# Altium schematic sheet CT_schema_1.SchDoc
size 538 x 519 mm
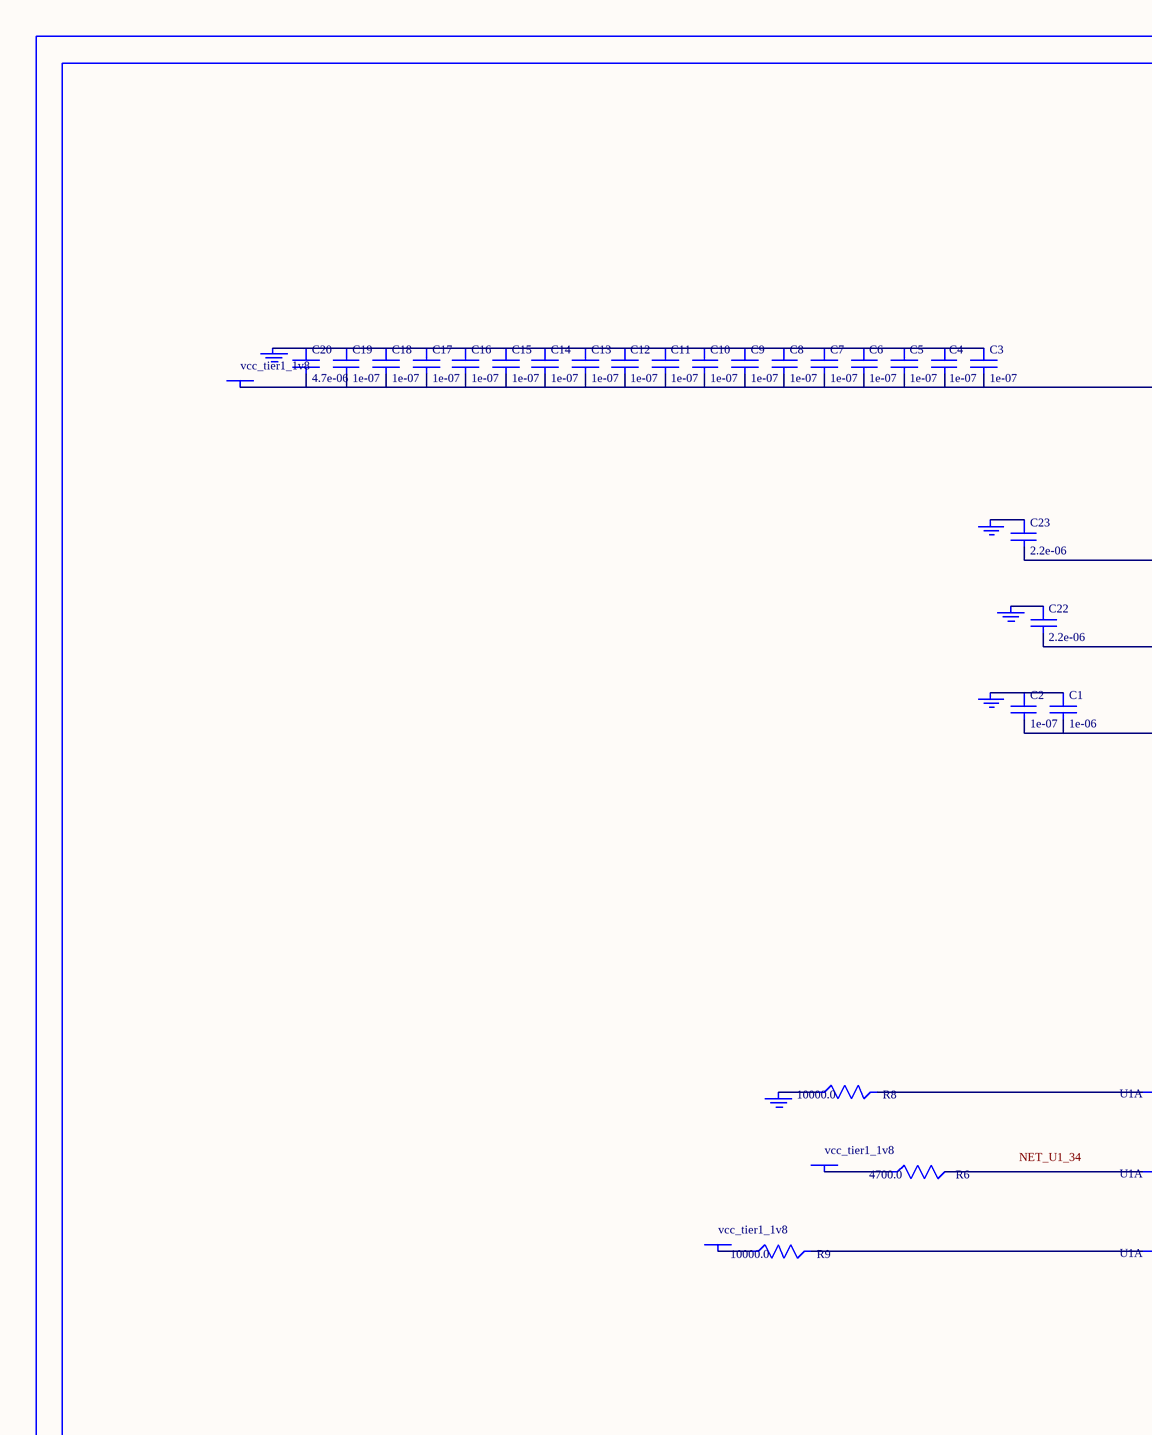
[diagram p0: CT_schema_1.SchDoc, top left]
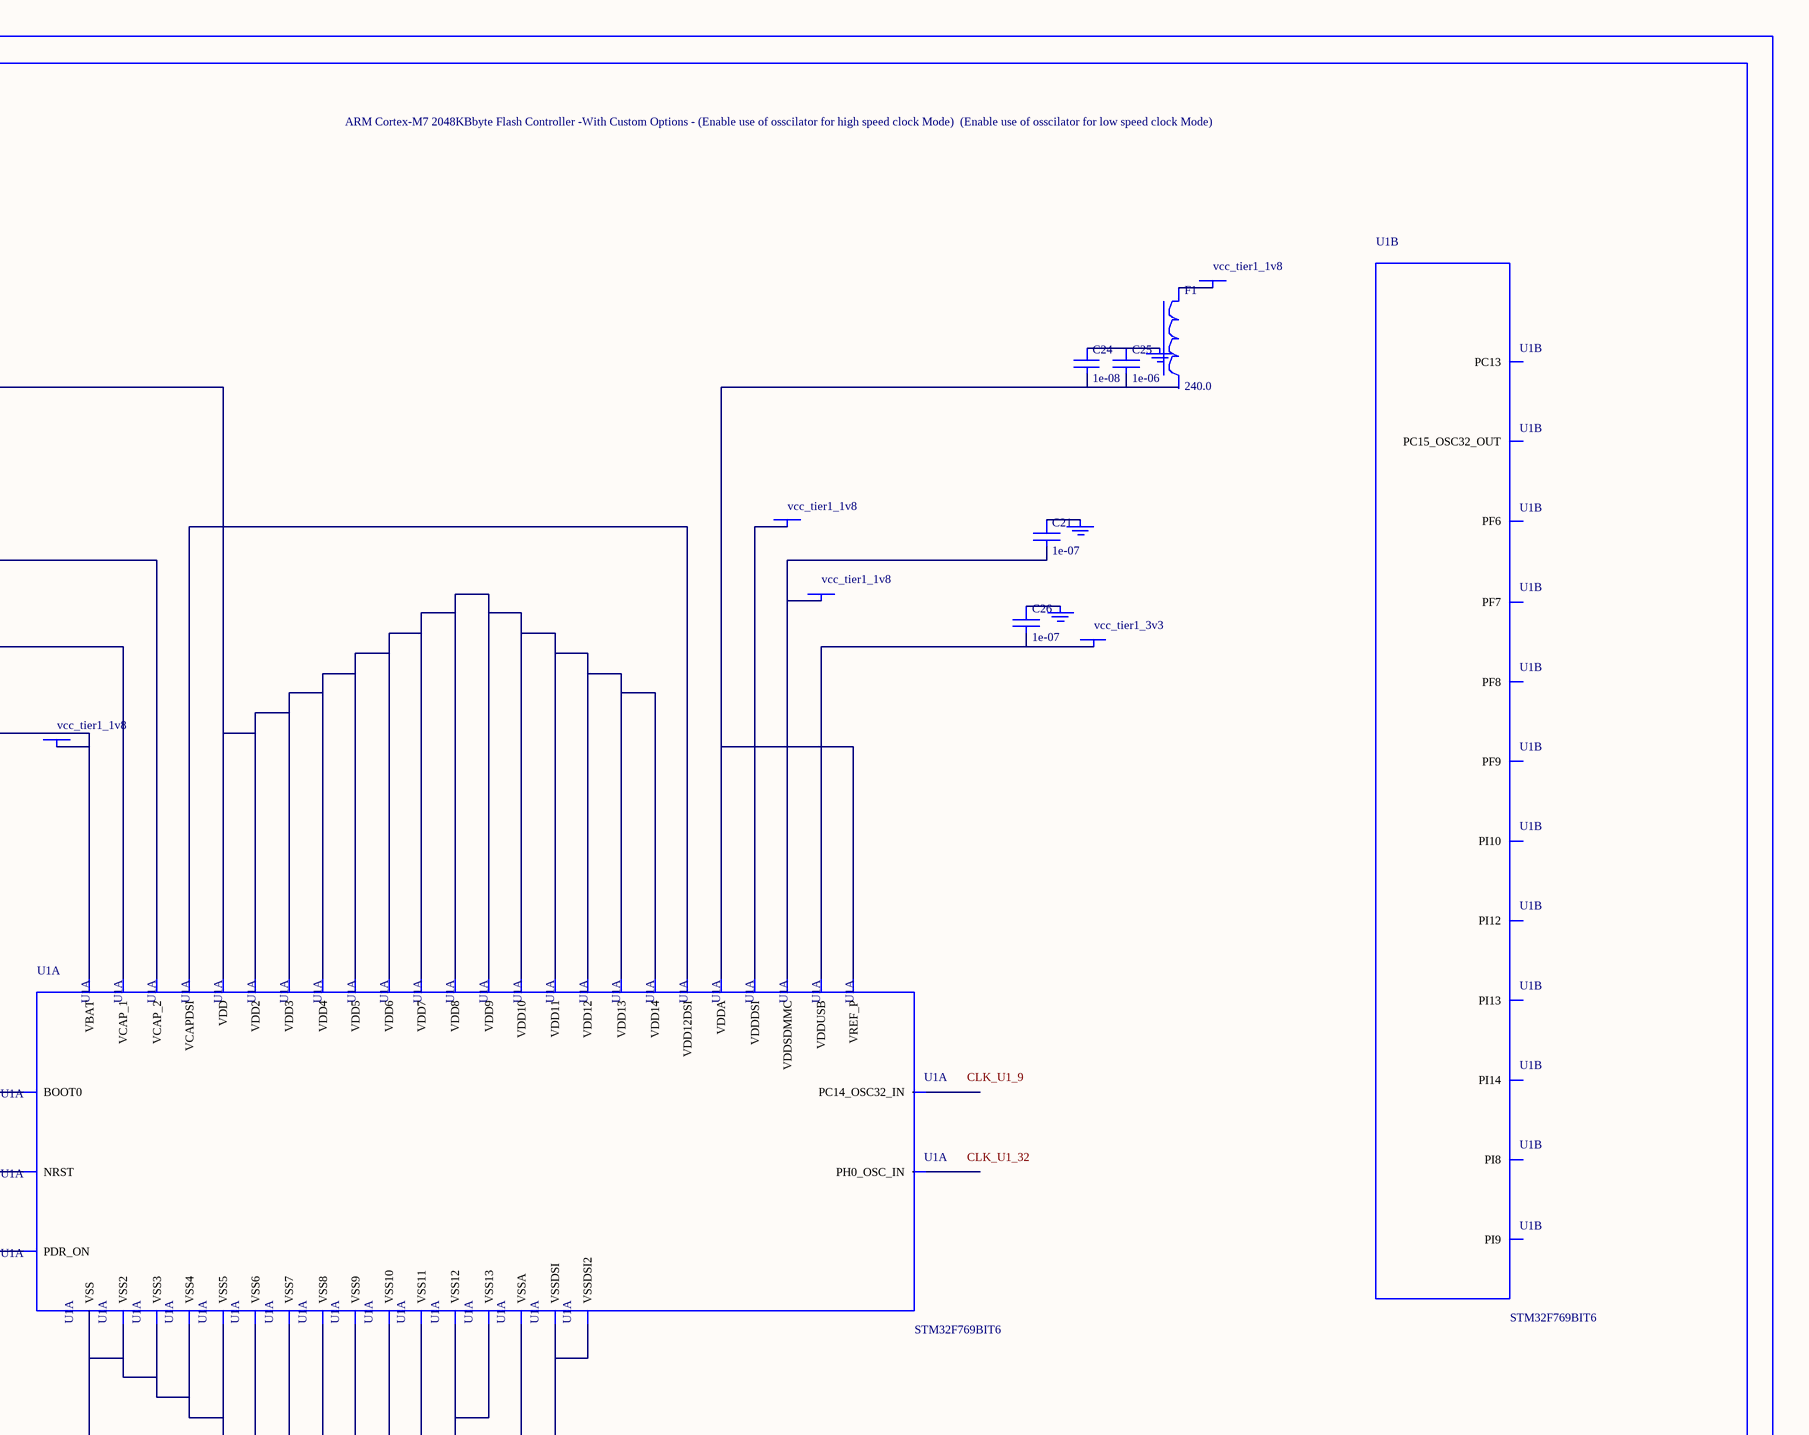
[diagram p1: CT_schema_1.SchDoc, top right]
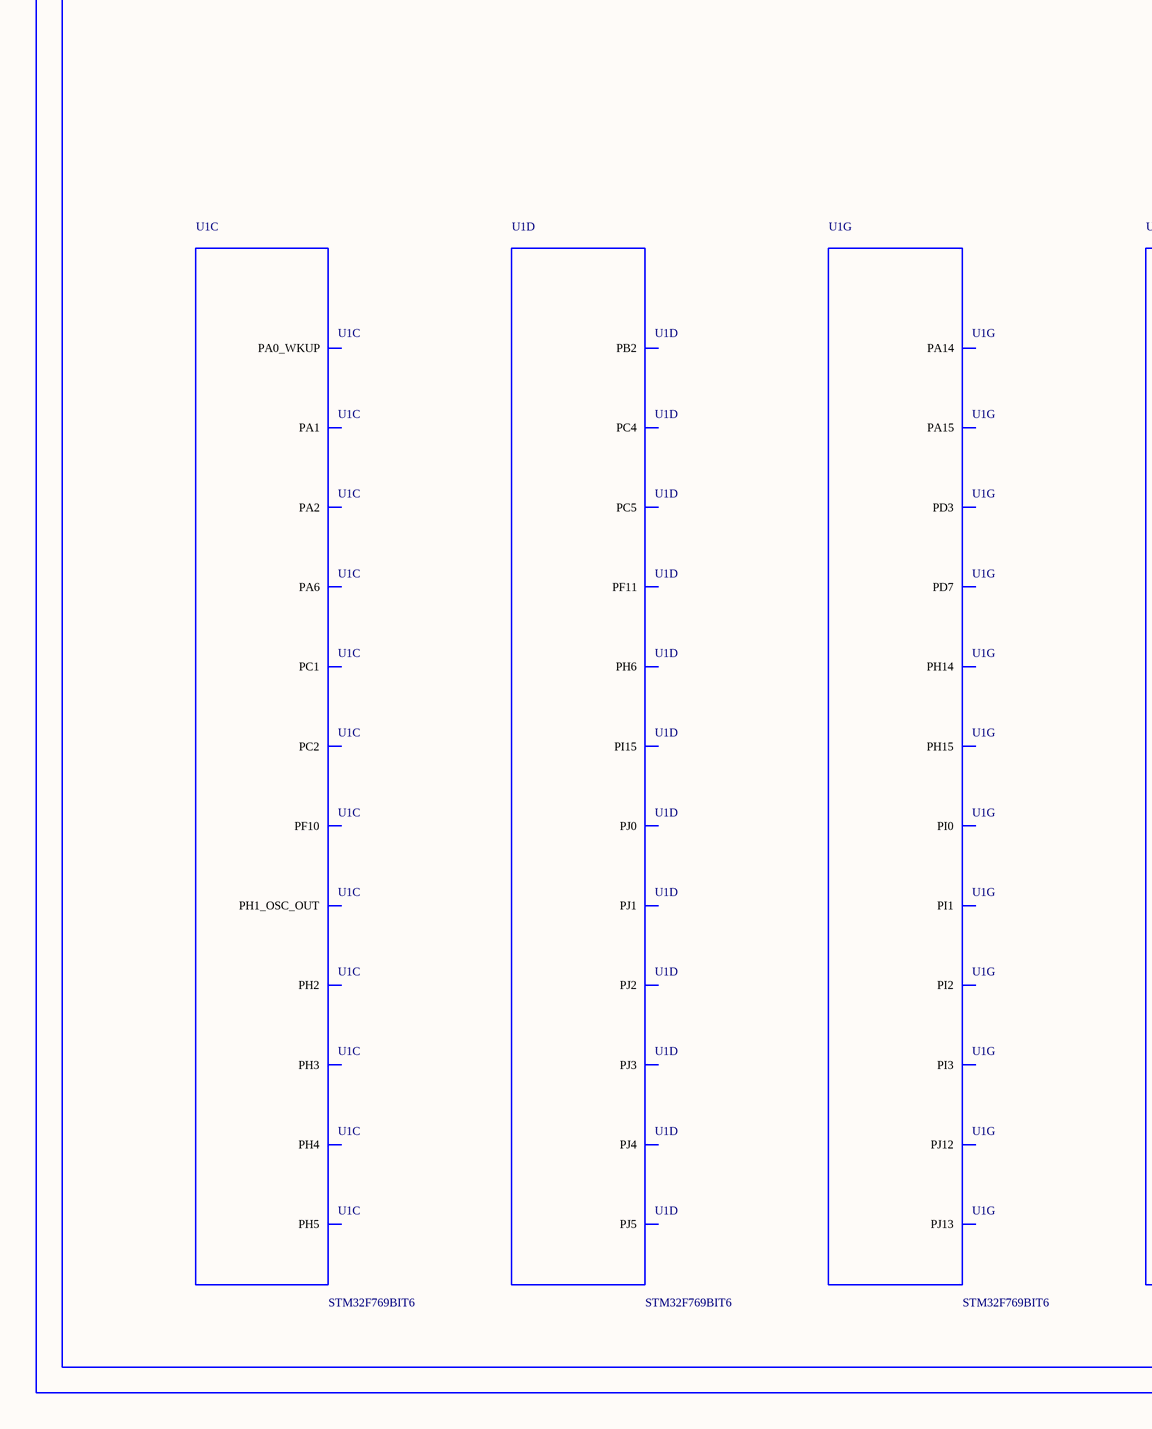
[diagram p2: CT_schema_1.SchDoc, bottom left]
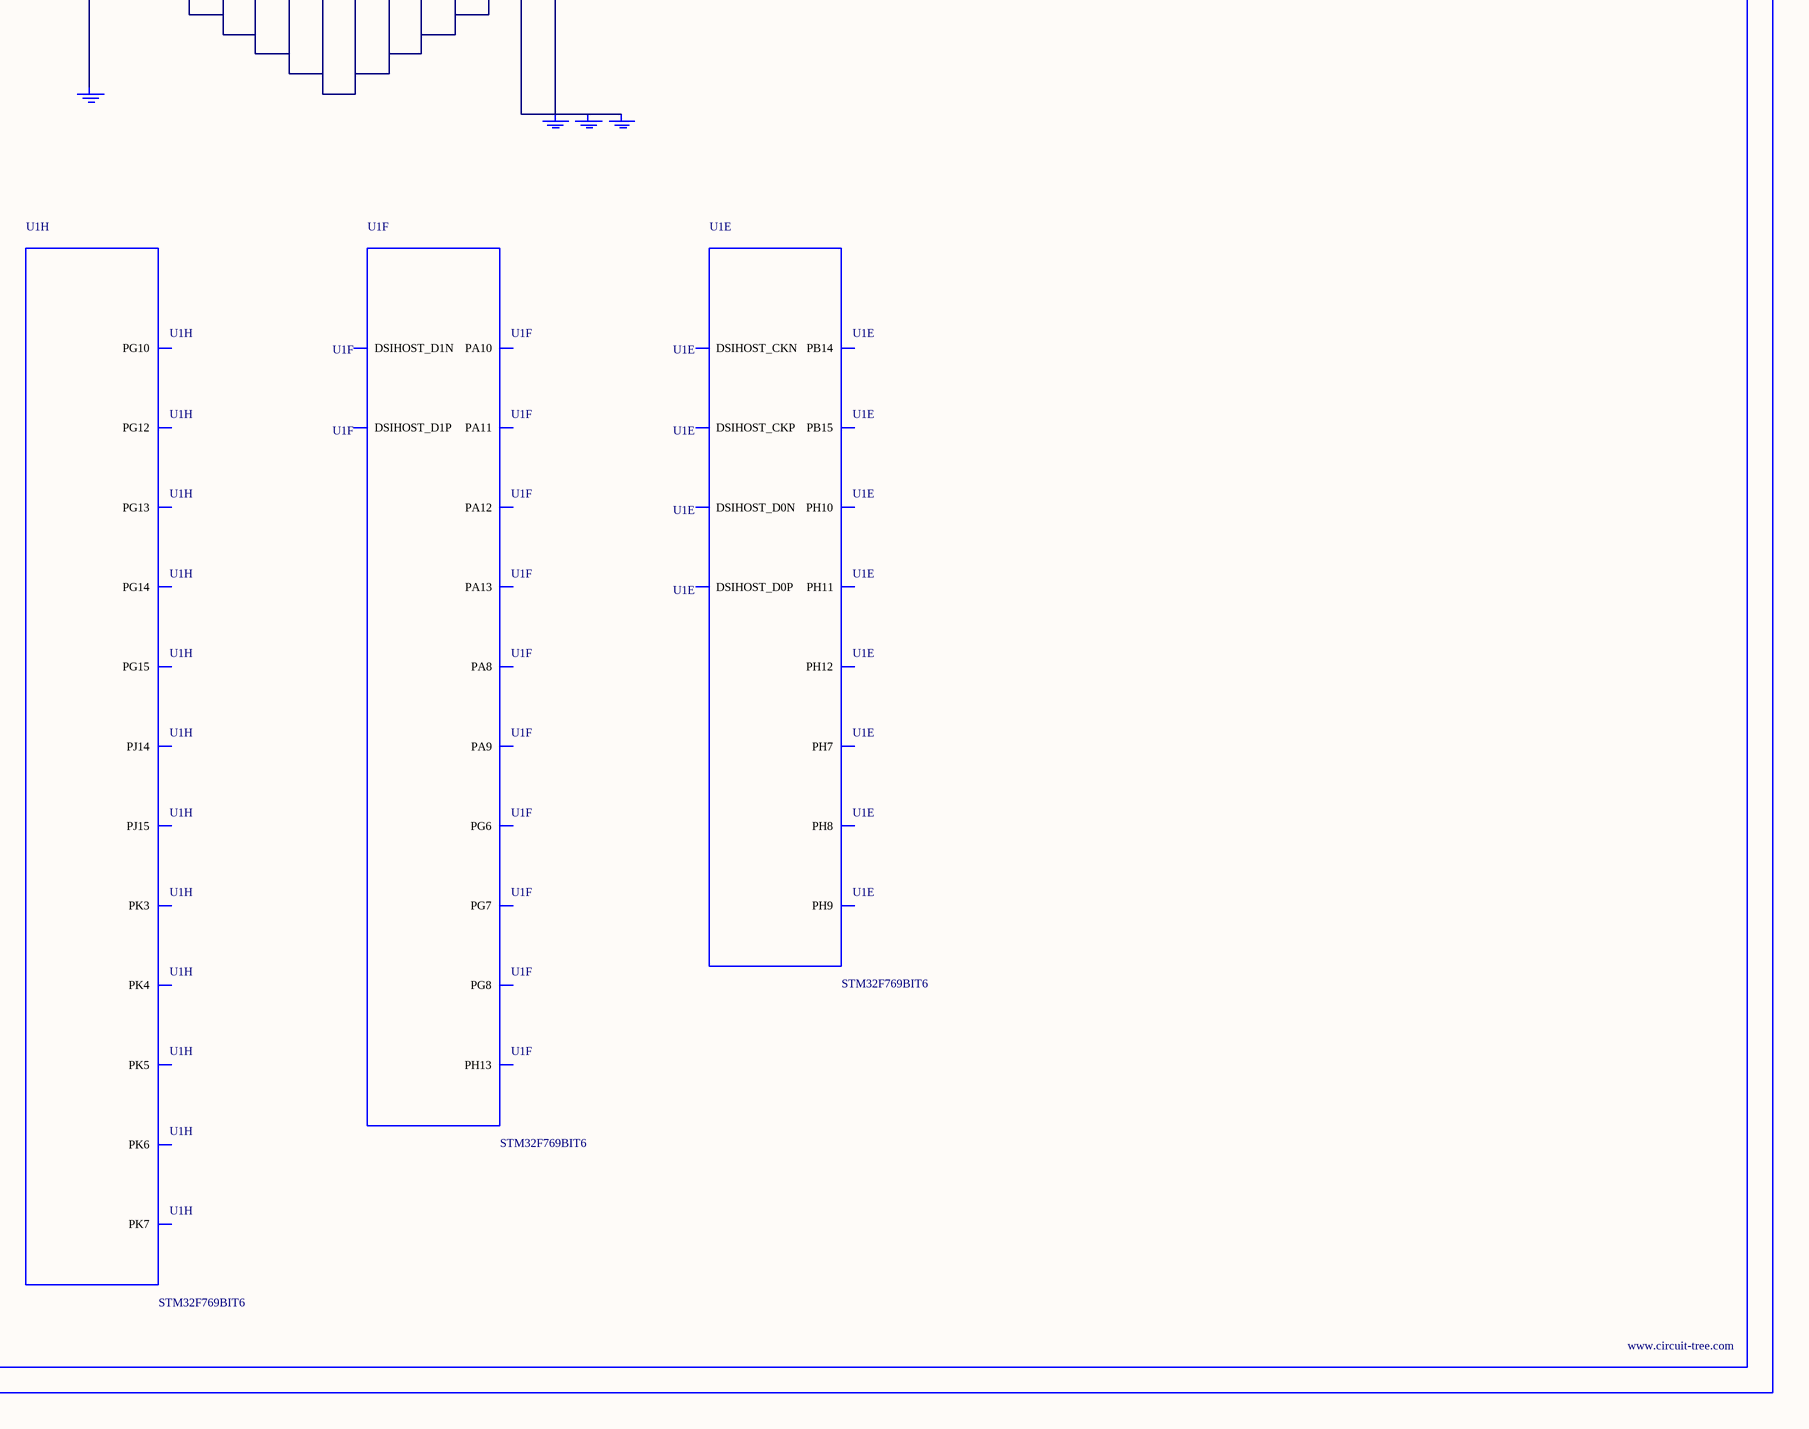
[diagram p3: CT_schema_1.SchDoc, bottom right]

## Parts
BORDER0  (no value)
C1  1e-06  [C0603]
C2  1e-07  [C0603]
C3  1e-07  [C0603]
C4  1e-07  [C0603]
C5  1e-07  [C0603]
C6  1e-07  [C0603]
C7  1e-07  [C0603]
C8  1e-07  [C0603]
C9  1e-07  [C0603]
C10  1e-07  [C0603]
C11  1e-07  [C0603]
C12  1e-07  [C0603]
C13  1e-07  [C0603]
C14  1e-07  [C0603]
C15  1e-07  [C0603]
C16  1e-07  [C0603]
C17  1e-07  [C0603]
C18  1e-07  [C0603]
C19  1e-07  [C0603]
C20  4.7e-06  [C0603]
C21  1e-07  [C0603]
C22  2.2e-06  [C0603]
C23  2.2e-06  [C0603]
C24  1e-08  [C0603]
C25  1e-06  [C0603]
C26  1e-07  [C0603]
F1  240.0  [L0603]
GND_INSTANCE_0_0  (no value)
GND_INSTANCE_0_1  (no value)
GND_INSTANCE_0_2  (no value)
GND_INSTANCE_0_3  (no value)
GND_INSTANCE_0_4  (no value)
GND_INSTANCE_0_5  (no value)
GND_INSTANCE_0_6  (no value)
GND_INSTANCE_0_7  (no value)
GND_INSTANCE_0_8  (no value)
GND_INSTANCE_0_9  (no value)
GND_INSTANCE_0_10  (no value)
GND_INSTANCE_0_11  (no value)
POWER_INSTANCE_0_0  vcc_tier1_1v8
POWER_INSTANCE_0_1  vcc_tier1_1v8
POWER_INSTANCE_0_2  vcc_tier1_1v8
POWER_INSTANCE_0_3  vcc_tier1_1v8
POWER_INSTANCE_0_4  vcc_tier1_3v3
POWER_INSTANCE_0_5  vcc_tier1_1v8
POWER_INSTANCE_0_6  vcc_tier1_1v8
POWER_INSTANCE_0_7  vcc_tier1_1v8
R6  4700.0  [R0603]
R8  10000.0  [R0603]
R9  10000.0  [R0603]
U1  STM32F769BIT6  [LQFP208]  (parts A,B,C,D,E,F,G,H of 15)

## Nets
NetC1_1: C1.1 C2.1 GND_INSTANCE_0_0.0(GND)
NetC1_2: C1.2 C2.2 POWER_INSTANCE_0_0.0(PWR) U1.6(VBAT)
NetC3_1: C3.1 C4.1 C5.1 C6.1 C7.1 C8.1 C9.1 C10.1 C11.1 C12.1 C13.1 C14.1 C15.1 C16.1 C17.1 C18.1 C19.1 C20.1 GND_INSTANCE_0_1.0(GND)
NetC3_2: C3.2 C4.2 C5.2 C6.2 C7.2 C8.2 C9.2 C10.2 C11.2 C12.2 C13.2 C14.2 C15.2 C16.2 C17.2 C18.2 C19.2 C20.2 POWER_INSTANCE_0_1.0(PWR) U1.15(VDD) U1.26(VDD2) U1.39(VDD3) U1.52(VDD4) U1.59(VDD5) U1.73(VDD6) U1.83(VDD7) U1.94(VDD8) U1.103(VDD9) U1.115(VDD10) U1.150(VDD11) U1.158(VDD12) U1.185(VDD13) U1.204(VDD14)
NetC21_1: C21.1 GND_INSTANCE_0_9.0(GND)
NetC21_2: C21.2 POWER_INSTANCE_0_5.0(PWR) U1.171(VDDSDMMC)
NetC22_1: C22.1 GND_INSTANCE_0_4.0(GND)
NetC22_2: C22.2 U1.92(VCAP_1)
NetC23_1: C23.1 GND_INSTANCE_0_8.0(GND)
NetC23_2: C23.2 U1.148(VCAP_2)
NetC24_1: C24.1 C25.1 GND_INSTANCE_0_3.0(GND)
NetC24_2: C24.2 C25.2 U1.41(VREF_P) U1.42(VDDA)
NetC26_1: C26.1 GND_INSTANCE_0_7.0(GND)
NetC26_2: C26.2 POWER_INSTANCE_0_4.0(PWR) U1.137(VDDUSB)
NetF1_1: F1.1 POWER_INSTANCE_0_2.0(PWR)
NetGND_INSTANCE_0_2_0: GND_INSTANCE_0_2.0(GND) GND_INSTANCE_0_5.0(GND) GND_INSTANCE_0_6.0(GND) U1.40(VSSA) U1.122(VSSDSI) U1.128(VSSDSI2)
NetGND_INSTANCE_0_10_0: GND_INSTANCE_0_10.0(GND) R8.1
NetGND_INSTANCE_0_11_0: GND_INSTANCE_0_11.0(GND) U1.14(VSS) U1.25(VSS2) U1.51(VSS3) U1.60(VSS4) U1.72(VSS5) U1.82(VSS6) U1.93(VSS7) U1.114(VSS8) U1.136(VSS9) U1.149(VSS10) U1.170(VSS11) U1.184(VSS12) U1.202(VSS13)
NetPOWER_INSTANCE_0_3_0: POWER_INSTANCE_0_3.0(PWR) U1.118(VDDDSI)
NetPOWER_INSTANCE_0_6_0: POWER_INSTANCE_0_6.0(PWR) R9.1
NetPOWER_INSTANCE_0_7_0: POWER_INSTANCE_0_7.0(PWR) R6.1
NetR6_2: R6.2 U1.34(NRST)
NetR8_2: R8.2 U1.197(BOOT0)
NetR9_2: R9.2 U1.203(PDR_ON)
NetU1_119: U1.119(VCAPDSI) U1.125(VDD12DSI)

Not connected (* = marked no-connect by the designer): F1 2; U1 7(PI8) 8(PC13) 9(PC14_OSC32_IN) 10(PC15_OSC32_OUT) 11(PI9) 12(PI10) 19(PI12) 20(PI13) 21(PI14) 27(PF6) 28(PF7) 29(PF8) 30(PF9) 31(PF10) 32(PH0_OSC_IN) 33(PH1_OSC_OUT) 36(PC1) 37(PC2) 43(PA0_WKUP) 44(PA1) 45(PA2) 46(PH2) 47(PH3) 48(PH4) 49(PH5) 55(PA6) 57(PC4) 58(PC5) 63(PB2) 64(PI15) 65(PJ0) 66(PJ1) 67(PJ2) 68(PJ3) 69(PJ4) 70(PF11) 95(PJ5) 96(PH6) 97(PH7) 98(PH8) 99(PH9) 100(PH10) 101(PH11) 102(PH12) 106(PB14) 107(PB15) 120(DSIHOST_D0P) 121(DSIHOST_D0N) 123(DSIHOST_CKP) 124(DSIHOST_CKN) 126(DSIHOST_D1P) 127(DSIHOST_D1N) 133(PG6) 134(PG7) 135(PG8) 142(PA8) 143(PA9) 144(PA10) 145(PA11) 146(PA12) 147(PA13) 151(PH13) 152(PH14) 153(PH15) 154(PI0) 155(PI1) 156(PI2) 157(PI3) 159(PA14) 160(PA15) 167(PD3) 173(PD7) 174(PJ12) 175(PJ13) 176(PJ14) 177(PJ15) 179(PG10) 181(PG12) 182(PG13) 183(PG14) 186(PK3) 187(PK4) 188(PK5) 189(PK6) 190(PK7) 191(PG15)

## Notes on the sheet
- Labels drawn without touching a wire or pin: CLK_U1_9, CLK_U1_32, NET_U1_34

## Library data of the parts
BORDER0 = BORDER_PAGE0
C1 C25 = C0603C105K3RACTU
C2-C19 C21 C26 = 06035C104K4Z2A
C20 = GRM188R6YA475KE15D
C22 C23 = C0603C225K8RACTU
C24 = 06035C103K4Z2A
F1 = Z0603C241ASMST
GND_INSTANCE_0_0-GND_INSTANCE_0_11 = GND
POWER_INSTANCE_0_0-POWER_INSTANCE_0_7 = PWR
R6 = RC0603JR-074K7L
R8 R9 = RC0603JR-0710KL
